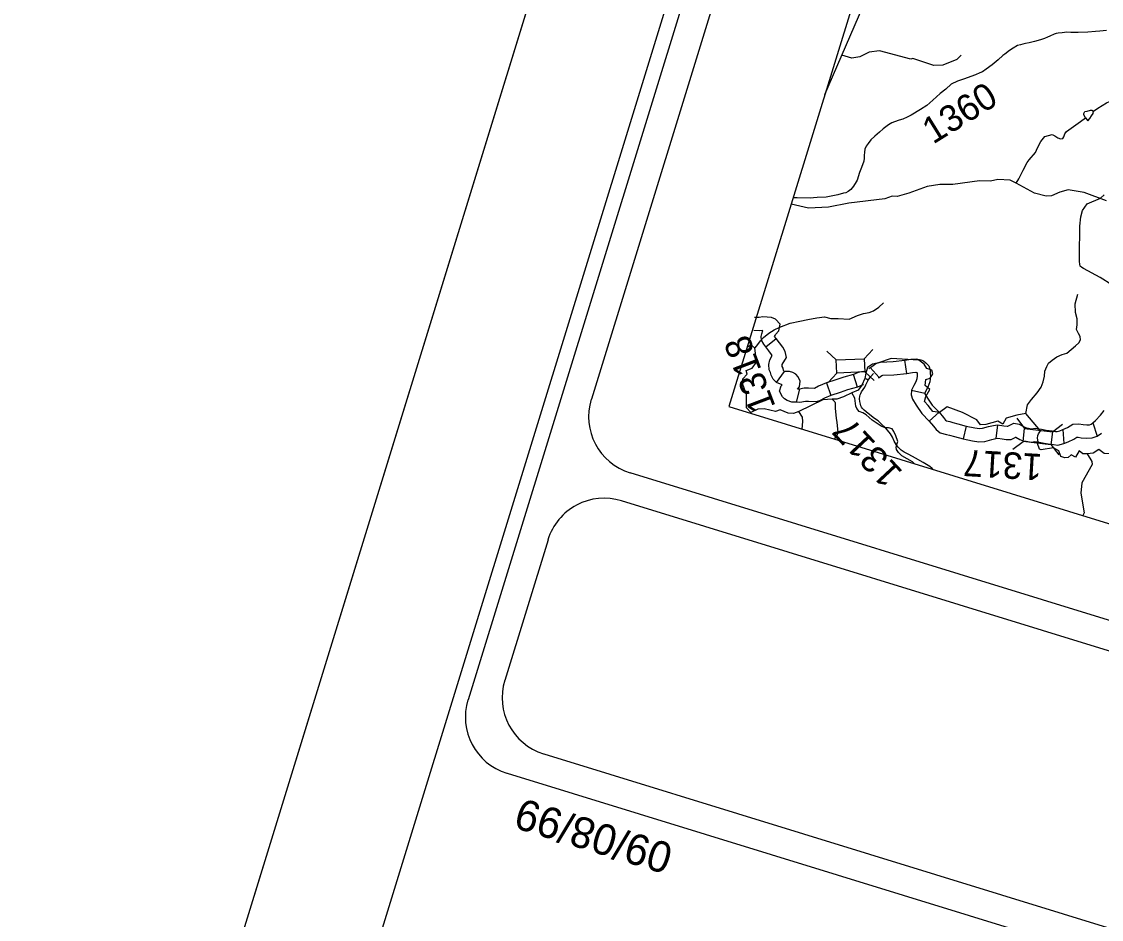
# Model space of a CAD drawing. Extents: x 1347947 to 1350662, y 1027710 to 1030532.
# Drawn here: x 1347946.9 to 1348130.6, y 1028682.4 to 1028835.1 of the extents above; entities that cross this region are included whole.
import ezdxf

# ---------------------------------------------------------------- set-up
doc = ezdxf.new("R2010")
doc.units = 0
for name, color, linetype in [('Default', 7, 'Continuous'), ('Prop Leader Line Light', 7, 'Continuous'), ('Prop WCC CELL', 7, 'Continuous'), ('Sheet Cutting Line CELL', 7, 'Continuous'), ('Sheet Plot Border Inside CELL', 7, 'Continuous'), ('Sheet Plot Border Outside CELL', 7, 'Continuous'), ('Sheet Title CELL', 7, 'Continuous')]:
    doc.layers.add(name, color=color, linetype=linetype)

msp = doc.modelspace()

# ---------------------------------------------------------------- linework, layer by layer
at = {"layer": 'Default'}
for p, q in [((1348073.5, 1028779.81), (1348075.27, 1028781.19)), ((1348083.87, 1028779.04), (1348085.47, 1028777.56)), ((1348090.24, 1028777.74), (1348091.71, 1028779.34)), ((1348092.76, 1028774.59), (1348091.22, 1028776.29)), ((1348097.46, 1028775.28), (1348097.15, 1028777.5)), ((1348075.29, 1028773.73), (1348076.66, 1028775.6)), ((1348084.08, 1028773.74), (1348085.56, 1028775.34)), ((1348089.11, 1028772.93), (1348088.38, 1028775.07)), ((1348090.32, 1028775.57), (1348091.92, 1028774.09)), ((1348079.19, 1028772.6), (1348078.66, 1028770.38)), ((1348083.79, 1028773.65), (1348084.57, 1028771.54)), ((1348098.26, 1028772.41), (1348100.51, 1028771.9)), ((1348102.95, 1028768.68), (1348101.28, 1028767.17)), ((1348116.19, 1028767.66), (1348117.52, 1028765.93)), ((1348129.12, 1028766.86), (1348129.88, 1028764.62)), ((1348107.55, 1028766.33), (1348107.05, 1028764.13)), ((1348112.92, 1028766.53), (1348112.63, 1028764.18)), ((1348122.25, 1028765.32), (1348123.97, 1028766.65)), ((1348124.02, 1028765.71), (1348124.21, 1028763.36)), ((1348115.52, 1028762.39), (1348117.24, 1028763.72)), ((1348121.98, 1028763.16), (1348123.31, 1028761.44))]:
    msp.add_line(p, q, dxfattribs=at)
for points in [[(1348083.52, 1028822.71), (1348089.97, 1028837.63), (1348104.26, 1028873.21), (1348113.82, 1028899.5), (1348162.49, 1029030.38), (1348171.57, 1029045.86), (1348180.52, 1029067.26), (1348186.85, 1029082.58), (1348194.68, 1029101.03), (1348199.8, 1029113.4)], [(1348131.42, 1028833.6), (1348130.32, 1028833.47), (1348129.55, 1028833.43), (1348128.27, 1028833.33), (1348126.61, 1028833.26), (1348125.4, 1028833.26), (1348124.69, 1028833.29), (1348123.89, 1028833.2), (1348123.23, 1028833.12), (1348122.89, 1028833.1), (1348122.52, 1028832.95), (1348121.8, 1028832.6), (1348121.4, 1028832.44), (1348120.87, 1028832.23), (1348120.23, 1028831.99), (1348119.17, 1028831.69), (1348118.31, 1028831.5), (1348117.66, 1028831.4), (1348117.23, 1028831.28), (1348116.8, 1028831.16), (1348116.28, 1028831.04), (1348115.56, 1028830.59), (1348114.96, 1028830.17), (1348114.17, 1028829.57), (1348113.83, 1028829.34), (1348113.03, 1028828.61), (1348111.98, 1028827.77), (1348110.97, 1028826.99), (1348110.36, 1028826.57), (1348109.9, 1028826.38), (1348109.13, 1028826.06), (1348107.11, 1028825.34), (1348106.11, 1028824.96), (1348105.02, 1028824.44), (1348104.1, 1028823.63), (1348103.12, 1028822.87), (1348101.9, 1028821.75), (1348100.9, 1028820.86), (1348099.8, 1028820.13), (1348098.23, 1028819.2), (1348097.54, 1028818.84), (1348096.78, 1028818.51), (1348096.17, 1028818.32), (1348095.4, 1028818.04), (1348094.95, 1028817.87), (1348094.37, 1028817.56), (1348093.44, 1028816.85), (1348092.82, 1028816.3), (1348092.03, 1028815.63), (1348091.33, 1028815.01), (1348090.88, 1028814.38), (1348090.53, 1028813.92), (1348090.33, 1028813.42), (1348090.29, 1028812.9), (1348090.23, 1028812.35), (1348090.21, 1028811.87), (1348090.15, 1028811.34), (1348089.79, 1028810.28), (1348089.44, 1028809.43), (1348089, 1028808.16), (1348088.83, 1028807.87), (1348088.39, 1028807.11), (1348087.94, 1028806.53), (1348087.52, 1028806.19), (1348087.07, 1028805.98), (1348086.77, 1028805.92), (1348086.7, 1028805.91), (1348085.74, 1028805.67), (1348083.75, 1028805.26), (1348082.23, 1028805.18), (1348081.62, 1028805.12), (1348081.01, 1028805.07), (1348078.82, 1028805.13), (1348078.11, 1028805.15)], [(1348106.72, 1028829.41), (1348105.96, 1028828.66), (1348103.59, 1028827.71), (1348102.04, 1028827.66), (1348098.47, 1028828.83), (1348098.15, 1028828.69), (1348092.8, 1028830.14), (1348091.08, 1028829.9), (1348089.47, 1028829.1), (1348088.1, 1028828.91), (1348086.41, 1028829.4)], [(1348127.85, 1028818.73), (1348127.59, 1028819.27), (1348127.56, 1028819.49), (1348127.78, 1028819.82), (1348128.14, 1028819.85), (1348128.74, 1028820.05), (1348128.92, 1028820.03), (1348129.23, 1028819.88)], [(1348129.23, 1028819.88), (1348129.96, 1028820.38), (1348131.44, 1028821.28), (1348131.93, 1028821.52), (1348132.52, 1028821.56), (1348133.6, 1028821.16), (1348134.22, 1028821.04), (1348135.17, 1028821.16), (1348136.07, 1028821.45)], [(1348116.05, 1028807.62), (1348116.55, 1028808.36), (1348117.28, 1028809.84), (1348117.95, 1028811.13), (1348118.3, 1028811.58), (1348119.35, 1028812.83), (1348119.69, 1028813.62), (1348120.27, 1028814.7), (1348120.93, 1028815.59), (1348122.18, 1028815.91), (1348122.66, 1028815.7), (1348123.14, 1028815.33), (1348123.6, 1028815.17), (1348123.99, 1028815.23), (1348124.21, 1028815.52), (1348124.35, 1028816.04), (1348124.62, 1028816.4), (1348127.03, 1028818.14), (1348127.85, 1028818.73)], [(1348127.85, 1028818.73), (1348128.24, 1028818.23), (1348128.62, 1028818.6), (1348128.89, 1028819.08), (1348129.19, 1028819.48), (1348129.23, 1028819.88)], [(1348131.47, 1028804.64), (1348127.63, 1028806.05), (1348124.93, 1028806.48), (1348123.51, 1028806.08), (1348122.11, 1028805.5), (1348121.2, 1028805.43), (1348119.22, 1028805.95), (1348116.05, 1028807.62), (1348115.06, 1028808.12), (1348112.97, 1028808.26), (1348111.69, 1028807.94), (1348109.84, 1028808), (1348105.28, 1028807.39), (1348103.08, 1028807.4), (1348100.92, 1028807.05), (1348097.79, 1028805.94), (1348095.82, 1028805.36), (1348095, 1028805.4), (1348093.72, 1028804.99), (1348087.61, 1028804.25), (1348084.12, 1028803.53), (1348080.74, 1028803.35), (1348077.78, 1028804.06)], [(1348132.36, 1028790.34), (1348130.39, 1028791.59), (1348127.53, 1028793.11), (1348127.24, 1028793.27), (1348126.97, 1028793.53), (1348126.88, 1028793.85), (1348126.85, 1028794.3), (1348126.86, 1028795.24), (1348126.9, 1028800.3), (1348127.09, 1028801.92), (1348127.36, 1028803), (1348128.17, 1028804.11), (1348130.4, 1028805.09), (1348131.02, 1028805.66)], [(1348071.59, 1028779.54), (1348071.96, 1028779.99), (1348072.58, 1028780.79), (1348073.09, 1028781.36), (1348073.99, 1028782.11), (1348074.89, 1028782.71), (1348075.87, 1028783.16), (1348077.62, 1028783.81), (1348079.29, 1028784.18), (1348080.65, 1028784.42), (1348082.15, 1028784.73), (1348083.47, 1028784.88), (1348084.57, 1028784.63), (1348085.78, 1028784.61), (1348087.66, 1028784.5), (1348089.11, 1028785.14), (1348090.1, 1028785.46), (1348091.07, 1028785.61), (1348091.83, 1028785.92), (1348092.72, 1028786.52), (1348093.49, 1028787.27)], [(1348117.74, 1028768.44), (1348118.02, 1028769.94), (1348118.69, 1028770.86), (1348119.65, 1028771.95), (1348120.34, 1028772.93), (1348120.66, 1028773.84), (1348120.89, 1028774.78), (1348120.96, 1028775.68), (1348121.27, 1028776.44), (1348121.56, 1028776.99), (1348122.22, 1028777.54), (1348123.02, 1028778.12), (1348123.92, 1028778.49), (1348124.67, 1028778.74), (1348126.17, 1028779.94), (1348126.73, 1028780.5), (1348127.04, 1028780.97), (1348126.99, 1028781.53), (1348126.67, 1028782.05), (1348126.34, 1028782.74), (1348126.45, 1028783.52), (1348126.46, 1028784.54), (1348126.17, 1028785.64), (1348126.13, 1028787.08), (1348126.54, 1028788.73)], [(1348090.52, 1028775.52), (1348090.04, 1028775.61), (1348089.2, 1028775.44), (1348088.38, 1028775.07), (1348086.73, 1028774.66), (1348085.4, 1028774.18), (1348083.79, 1028773.65), (1348082.44, 1028773.1), (1348081.77, 1028772.71), (1348080.76, 1028772.76), (1348080.01, 1028772.74), (1348079.19, 1028772.6), (1348078.9, 1028772.62), (1348079.23, 1028773), (1348079.35, 1028773.96), (1348078.99, 1028774.69), (1348078.58, 1028775.13), (1348078.07, 1028775.42), (1348077.52, 1028775.61), (1348076.66, 1028775.6), (1348076.59, 1028775.62), (1348076.57, 1028775.65), (1348076.49, 1028775.79), (1348076.41, 1028776.16), (1348076.29, 1028776.43), (1348076.28, 1028776.69), (1348076.29, 1028776.78), (1348077.02, 1028778), (1348076.76, 1028778.98), (1348076.38, 1028779.71), (1348075.81, 1028780.45), (1348075.27, 1028781.19), (1348074.99, 1028781.53), (1348075.06, 1028781.73), (1348075.15, 1028781.89), (1348075.69, 1028782.52), (1348075.92, 1028783.63), (1348075.15, 1028784.51), (1348074.44, 1028784.78), (1348073.74, 1028784.86), (1348072.99, 1028784.87), (1348072.37, 1028784.76), (1348071.57, 1028784.81)], [(1348090.11, 1028773.31), (1348090.06, 1028773.32), (1348089.9, 1028773.28), (1348089.11, 1028772.93), (1348087.38, 1028772.5), (1348086.14, 1028772.05), (1348084.57, 1028771.54), (1348083.44, 1028771.08), (1348082.61, 1028770.6), (1348082.03, 1028770.45), (1348080.75, 1028770.51), (1348080.23, 1028770.49), (1348079.28, 1028770.33), (1348078.66, 1028770.38), (1348077.91, 1028770.37), (1348077.1, 1028770.66), (1348076.66, 1028770.96), (1348076.32, 1028771.3), (1348075.79, 1028772.25), (1348076.08, 1028773.14), (1348076.24, 1028773.34), (1348075.29, 1028773.73), (1348074.73, 1028774.32), (1348074.37, 1028774.99), (1348074.26, 1028775.45), (1348074.07, 1028775.91), (1348074.02, 1028776.81), (1348074.14, 1028777.57), (1348074.58, 1028778.3), (1348074.47, 1028778.5), (1348074.01, 1028779.11), (1348073.5, 1028779.81), (1348073.13, 1028780.25), (1348072.74, 1028780.95), (1348072.72, 1028781.57), (1348072.78, 1028781.99), (1348072.96, 1028782.58), (1348072.49, 1028782.5), (1348071.44, 1028782.56)], [(1348070.32, 1028775.17), (1348070.16, 1028775.77), (1348071.15, 1028776.14), (1348071.89, 1028777.17), (1348071.74, 1028778.71), (1348071.59, 1028779.54), (1348071.02, 1028780.11), (1348070.61, 1028779.86), (1348070.29, 1028779.74)], [(1348119.77, 1028764.74), (1348119.9, 1028764.98), (1348120.24, 1028765.49), (1348117.74, 1028768.44), (1348116.19, 1028768.18), (1348114.39, 1028767.64), (1348113.82, 1028766.64), (1348112.93, 1028767.14), (1348110.89, 1028766.59), (1348110.02, 1028766.55), (1348109.36, 1028767.37), (1348106.93, 1028768.65), (1348104.34, 1028769.57), (1348103.02, 1028768.62), (1348101.88, 1028768.79), (1348101.08, 1028769.84), (1348100.5, 1028770.49), (1348100.68, 1028771.34), (1348101.37, 1028772.52), (1348100.58, 1028773.23), (1348100.7, 1028774.26), (1348101.43, 1028774.45), (1348101.87, 1028775.18), (1348101.72, 1028775.82), (1348100.88, 1028776.13), (1348100.41, 1028776.86), (1348099.52, 1028777.5), (1348094.82, 1028777.8), (1348092.68, 1028777.05), (1348091.66, 1028776.87), (1348090.81, 1028776.27), (1348090.51, 1028775.34), (1348090.31, 1028774.41)], [(1348090.99, 1028776.03), (1348091.22, 1028776.29), (1348091.52, 1028776.47), (1348091.72, 1028776.61), (1348092.21, 1028776.95), (1348092.97, 1028777.2), (1348095.13, 1028777.29), (1348097.15, 1028777.5), (1348098.16, 1028777.68), (1348099.13, 1028777.74), (1348099.83, 1028777.61), (1348100.31, 1028777.39), (1348100.71, 1028777.07), (1348101.21, 1028776.54), (1348101.43, 1028775.85), (1348101.47, 1028775.29), (1348101.48, 1028774.75), (1348101.36, 1028773.86), (1348101.05, 1028772.94), (1348100.65, 1028772.18), (1348100.51, 1028771.9), (1348100.53, 1028771.83), (1348100.97, 1028771.09), (1348101.79, 1028769.87), (1348102.95, 1028768.68), (1348103.72, 1028767.75), (1348104.06, 1028767.34), (1348104.2, 1028767.22), (1348104.79, 1028767.07), (1348105.31, 1028766.92), (1348106.14, 1028766.7), (1348107.55, 1028766.33), (1348109.06, 1028766.03), (1348109.85, 1028765.9), (1348110.36, 1028765.94), (1348111.39, 1028766.24), (1348112.2, 1028766.39), (1348112.92, 1028766.53), (1348114, 1028766.36), (1348114.55, 1028766.29), (1348114.68, 1028766.28), (1348114.88, 1028766.39), (1348115.69, 1028766.83), (1348116.6, 1028766.67), (1348117.12, 1028766.37), (1348117.65, 1028766.08), (1348117.83, 1028766.01), (1348118.15, 1028765.96), (1348118.67, 1028765.87), (1348119.28, 1028765.94), (1348119.92, 1028765.86)], [(1348072.14, 1028769.19), (1348070.93, 1028768.61), (1348070.18, 1028769.44), (1348070.18, 1028771.69), (1348069.6, 1028773.38), (1348069.6, 1028774.37), (1348070.32, 1028775.17)], [(1348090.31, 1028774.41), (1348089.8, 1028773.28), (1348089.19, 1028772.45), (1348088.14, 1028771.95), (1348086.68, 1028771.3), (1348085.56, 1028770.91), (1348084.77, 1028770.89), (1348083.16, 1028770.8), (1348079.1, 1028768.77), (1348078.2, 1028768.45), (1348077.31, 1028768.5), (1348075.93, 1028769.07), (1348075.11, 1028768.79), (1348073.19, 1028769.24), (1348072.14, 1028769.19)], [(1348101.98, 1028758.94), (1348101.79, 1028759.09), (1348101.37, 1028759.44), (1348100.28, 1028760.11), (1348098.97, 1028760.85), (1348097.81, 1028761.46), (1348097.02, 1028761.89), (1348096.5, 1028762.21), (1348095.99, 1028762.72), (1348095.67, 1028763.17), (1348095.33, 1028763.76), (1348095.05, 1028764.45), (1348094.72, 1028765.02), (1348093.92, 1028765.96), (1348093.12, 1028766.69), (1348092.57, 1028767.2), (1348091.98, 1028767.63), (1348090.87, 1028768.44), (1348090.21, 1028769.02), (1348089.92, 1028769.32), (1348089.77, 1028769.52), (1348089.66, 1028769.74), (1348089.6, 1028770.05), (1348089.5, 1028770.52), (1348089.44, 1028770.98), (1348089.47, 1028771.41), (1348089.52, 1028771.63), (1348089.63, 1028771.86), (1348089.78, 1028772.13), (1348090.07, 1028772.54), (1348090.33, 1028772.96), (1348090.52, 1028773.33), (1348090.68, 1028773.69), (1348090.89, 1028774.12)], [(1348090.89, 1028774.12), (1348090.59, 1028774.32), (1348090.31, 1028774.41)], [(1348090.89, 1028774.12), (1348091.36, 1028774.76), (1348091.83, 1028775.28)], [(1348092.66, 1028774.52), (1348092.68, 1028774.54), (1348092.76, 1028774.59), (1348092.99, 1028774.75), (1348093.23, 1028774.92), (1348093.38, 1028774.97), (1348095.29, 1028775.04), (1348097.46, 1028775.28), (1348098.42, 1028775.44), (1348098.99, 1028775.48), (1348099.14, 1028775.45), (1348099.17, 1028775.42), (1348099.21, 1028775.38), (1348099.22, 1028775.2), (1348099.22, 1028774.87), (1348099.16, 1028774.37), (1348098.98, 1028773.83), (1348098.64, 1028773.2), (1348098.26, 1028772.41), (1348098.23, 1028771.66), (1348098.46, 1028770.91), (1348099.07, 1028769.89), (1348100.03, 1028768.45), (1348101.28, 1028767.17), (1348101.99, 1028766.31), (1348102.47, 1028765.73), (1348103.17, 1028765.16), (1348104.2, 1028764.9), (1348104.71, 1028764.75), (1348105.56, 1028764.52), (1348107.05, 1028764.13), (1348108.67, 1028763.82), (1348109.74, 1028763.64), (1348110.76, 1028763.71), (1348111.91, 1028764.05), (1348112.63, 1028764.18), (1348112.96, 1028764.25), (1348113.67, 1028764.14), (1348114.36, 1028764.04), (1348115.2, 1028764.02), (1348115.93, 1028764.4), (1348115.98, 1028764.43), (1348116.01, 1028764.41), (1348116.7, 1028764.04), (1348117.25, 1028763.82), (1348117.79, 1028763.74), (1348118.6, 1028763.6), (1348119.26, 1028763.67), (1348119.62, 1028763.63)], [(1348084.77, 1028770.89), (1348085.22, 1028770.43), (1348085.28, 1028770.3), (1348085.29, 1028769.28), (1348085.47, 1028767.65), (1348085.57, 1028766.94), (1348085.71, 1028765.26), (1348085.65, 1028764.91), (1348085.56, 1028764.64), (1348085.33, 1028764.47), (1348085.24, 1028764.2), (1348085.24, 1028764.09)], [(1348098.8, 1028759.92), (1348098.42, 1028760.22), (1348096.65, 1028761.27), (1348096.05, 1028761.82), (1348095.71, 1028762.31), (1348095.68, 1028762.73), (1348095.85, 1028763.33), (1348095.92, 1028763.71), (1348095.6, 1028764.66), (1348095.28, 1028765.38), (1348094.99, 1028765.83), (1348094.38, 1028766), (1348093.78, 1028766.03), (1348093.11, 1028766.29), (1348091.58, 1028767.33), (1348090.53, 1028768.22), (1348089.98, 1028768.57), (1348089.34, 1028768.79), (1348088.97, 1028769.31), (1348088.81, 1028769.72), (1348088.63, 1028771.06), (1348088.14, 1028771.95)], [(1348079.69, 1028765.8), (1348079.78, 1028767.07), (1348079.7, 1028767.81), (1348079.1, 1028768.77)], [(1348119.94, 1028765.85), (1348120.39, 1028765.78), (1348121.2, 1028765.63), (1348122.19, 1028765.5), (1348122.77, 1028765.41), (1348123.04, 1028765.37), (1348123.49, 1028765.5), (1348124.02, 1028765.71), (1348124.82, 1028766.1), (1348125.72, 1028766.62), (1348126.72, 1028766.7), (1348127.45, 1028766.57), (1348128.07, 1028766.51), (1348128.56, 1028766.55), (1348128.82, 1028766.63), (1348129.12, 1028766.86), (1348129.55, 1028767.28), (1348130.41, 1028768.17), (1348131.07, 1028768.95)], [(1348144.64, 1028769.39), (1348143.9, 1028768.83), (1348141.09, 1028769.51), (1348140.51, 1028769.5), (1348139.85, 1028769.82), (1348138.1, 1028769.84), (1348136.9, 1028768.84), (1348135.79, 1028765.17), (1348136.15, 1028764.16), (1348134.82, 1028762.33), (1348133.8, 1028762), (1348133.35, 1028761.55), (1348131.07, 1028761.64), (1348130.13, 1028762.36), (1348129.18, 1028761.69), (1348128.14, 1028761.61), (1348128.14, 1028761.61)], [(1348119.59, 1028763.63), (1348120.01, 1028763.56), (1348120.84, 1028763.41), (1348121.87, 1028763.27), (1348122.43, 1028763.18), (1348123.19, 1028763.07), (1348124.21, 1028763.36), (1348124.94, 1028763.65), (1348125.88, 1028764.12), (1348126.41, 1028764.42), (1348126.61, 1028764.44), (1348127.14, 1028764.34), (1348128.05, 1028764.25), (1348129.01, 1028764.32), (1348129.88, 1028764.62), (1348130.58, 1028765.14)], [(1348128.14, 1028761.61), (1348127.43, 1028761.61), (1348126.81, 1028762.1), (1348126.17, 1028761.01), (1348125.41, 1028761.42), (1348124.9, 1028760.99), (1348124.37, 1028760.92), (1348123.67, 1028761.17), (1348123.32, 1028762.1), (1348122.4, 1028762.64), (1348120.34, 1028762.27), (1348120.02, 1028762.4), (1348119.71, 1028763.33), (1348119.79, 1028763.64), (1348119.68, 1028764.26), (1348119.77, 1028764.74)], [(1348128.14, 1028761.61), (1348128.95, 1028760.3), (1348129.01, 1028759.78), (1348127.25, 1028756.65), (1348127.05, 1028754.93), (1348127.66, 1028751.58), (1348127.4, 1028751.11)]]:
    msp.add_lwpolyline(points, dxfattribs=at)
for points in [[(1348085.47, 1028777.56), (1348090.24, 1028777.75), (1348090.33, 1028775.53), (1348085.56, 1028775.34)], [(1348117.52, 1028765.93), (1348122.25, 1028765.33), (1348121.97, 1028763.12), (1348117.24, 1028763.72)]]:
    msp.add_lwpolyline(points, close=True, dxfattribs=at)
at = {"layer": 'Prop WCC CELL'}
for p, q in [((1348175.36, 1029120.93), (1348067.18, 1028769.65)), ((1348067.18, 1028769.65), (1348285.23, 1028702.5))]:
    msp.add_line(p, q, dxfattribs=at)
at = {"layer": 'Sheet Cutting Line CELL'}
msp.add_line((1347946.88, 1028557.97), (1348442.51, 1030167.38), dxfattribs=at)
at = {"layer": 'Sheet Plot Border Inside CELL'}
msp.add_lwpolyline([(1348980.53, 1028253.25), (1349471, 1029845.94), (1348462.64, 1030156.47), (1347972.16, 1028563.78)], close=True, dxfattribs=at)
at = {"layer": 'Sheet Plot Border Outside CELL'}
msp.add_lwpolyline([(1348442.51, 1030167.38), (1347946.88, 1028557.97), (1348998.14, 1028234.22), (1349493.77, 1029843.63)], close=True, dxfattribs=at)
at = {"layer": 'Sheet Title CELL'}
for p, q in [((1348848.45, 1028512.61), (1348050.43, 1028758.36)), ((1349023.78, 1028453.38), (1348048.96, 1028753.59))]:
    msp.add_line(p, q, dxfattribs=at)
for points in [[(1348458.46, 1030134.23), (1348022.85, 1028719.76)], [(1348461.76, 1030127.97), (1348043.83, 1028770.87)], [(1348036.47, 1028746.97), (1348029.1, 1028723.08)], [(1348035.72, 1028710.59), (1349010.54, 1028410.38)], [(1348029.47, 1028707.27), (1349013.84, 1028404.13)], [(1348029.47, 1028707.27), (1349013.84, 1028404.13)]]:
    msp.add_lwpolyline(points, dxfattribs=at)
for centre, start, end in [((1348053.33, 1028767.94), 162.8834, 252.8834), ((1348045.97, 1028744.05), 72.8834, 162.8834), ((1348038.62, 1028720.15), 162.8834, 252.8834), ((1348032.37, 1028716.85), 162.8834, 252.8834)]:
    msp.add_arc(centre, 10, start, end, dxfattribs=at)

# ---------------------------------------------------------------- texts
at = {"layer": 'Prop Leader Line Light'}
for s, rotation, p in [('1360', 31.8633, (1348101.93, 1028814.16)), ('1318', 110.809, (1348075.2, 1028769.63)), ('1317', 133.0846, (1348096.96, 1028758.5)), ('1317', 176.6667, (1348120.6, 1028761.55))]:
    msp.add_text(s, height=4.5, rotation=rotation, dxfattribs=at).set_placement(p)
at = {"layer": 'Sheet Title CELL'}
msp.add_text('09/08/99', height=5.25, rotation=162.8834, dxfattribs=at).set_placement((1348058.02, 1028695.08))

doc.saveas('drawing.dxf')
